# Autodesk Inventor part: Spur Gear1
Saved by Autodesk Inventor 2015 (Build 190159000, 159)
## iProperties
Created: 2014-06
Part Number: Spur Gear1
Material: Steel
Document SubType Name: Modeling
Designer: User
Categories: <?xml version="1.0" encoding="UTF-16"?> <MemberInstance><Categories><FamilyTemplate><FamilyTemplateParameter ValueType="xs:double" Id="1" ObjectReferenceKey="da
Density: 1 g/cm^3
Appearance: Steel
CustomPartVersion: 1
Author: User
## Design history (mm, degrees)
sketch "Sketch1"
  geometry: C1 r 9.449 at (0, 0)
  constraints: 1 centre point
  dimensions: "d0" = 18.89761 diameter of C1 (= da_da)
extrude "Extrusion1" new body sketch "Sketch1" distance "d1" = 4 (= da_b); taper "d2" = 0 deg
workplane "Work Plane2"
sketch "Sketch2"
  geometry: C1 r 9.449 at (0, 0) reference; C2 r 8.75 at (0, 0)
  constraints: 1 centre point, 1 coincident
  dimensions: "d3" = 17.5 diameter of C2 (= da_dw)
feature "Pitch Diameter" sketch "Sketch2" dims "d4" = 10, "d5" = 0
workplane "Work Plane8"
workplane "Work Plane9"
feature "Spur Gear" dims "da_b" = 4, "da_d" = 17.36192, "da_aw" = 17.5, "da_da" = 18.89761, "da_df" = 15.75239, "da_dw" = 17.5, angle "da_beta" = 40 deg, "da_lefttooth" = 10, "da_righttooth" = 0
body "Solid1"
body "Srf1"
other parameters: "d16" = 17.5 (= da_aw), "d17" = 0, "d34" = 1.65347 (computed from da_z), "d39" = 0, "d41" = 0, "d43" = 17.5 (= da_aw), "d46" = 17.5 (= da_aw), "d47" = 0, "d48" = 0
